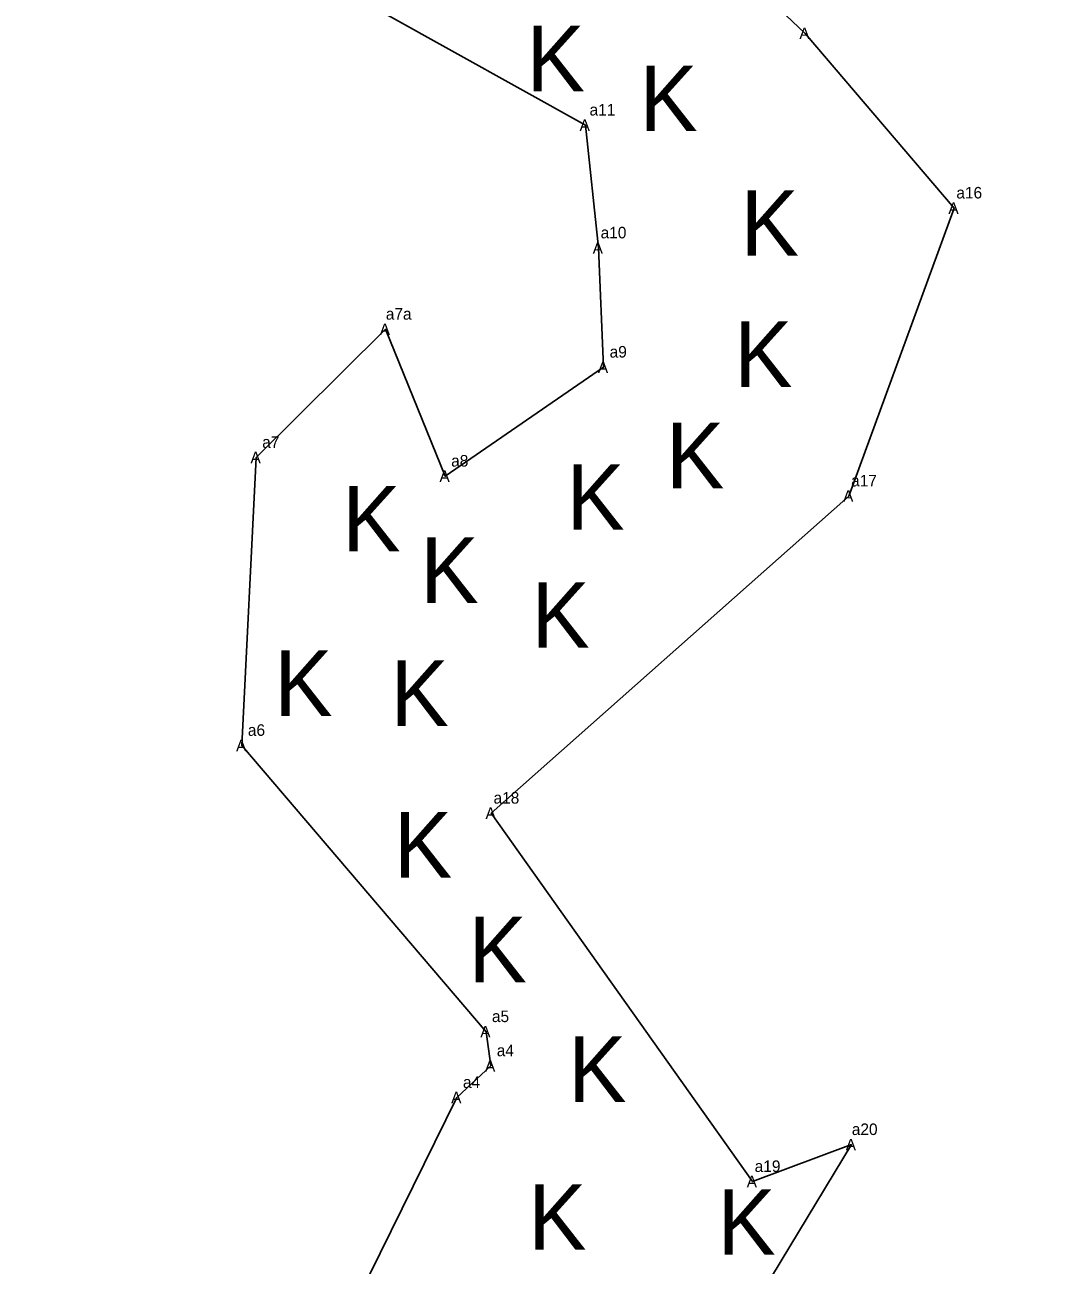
# Model space of a CAD drawing. Extents: x 2028512 to 2029541, y 737100 to 738747.
# Drawn here: x 2028890.6 to 2029023.1, y 738237.8 to 738398.9 of the extents above; entities that cross this region are included whole.
import ezdxf

# ---------------------------------------------------------------- set-up
doc = ezdxf.new("R2010")
doc.units = 0
for name, color, linetype in [('Old_Level_10', 7, 'Continuous'), ('Old_Level_20', 7, 'Continuous'), ('Old_Level_52', 7, 'Continuous'), ('Old_Level_61', 7, 'Continuous')]:
    doc.layers.add(name, color=color, linetype=linetype)

msp = doc.modelspace()

# ---------------------------------------------------------------- linework, layer by layer
at = {"layer": 'Old_Level_52'}
for points in [[(2028904.65, 738196.15), (2028890.57, 738227.25), (2028922.11, 738225.85), (2028932.53, 738230.73), (2028946.73, 738259.58), (2028951.13, 738263.7), (2028950.51, 738268.13), (2028918.78, 738305.31), (2028920.65, 738342.72), (2028937.45, 738359.38), (2028945.21, 738340.29), (2028965.8, 738354.45), (2028965.12, 738369.93), (2028963.42, 738385.89), (2028937.56, 738400.24), (2028943.82, 738411.81), (2028965.6, 738422.83), (2028991.98, 738397.81)], [(2028991.98, 738397.81), (2029011.35, 738375.11), (2028997.67, 738337.71), (2028951.19, 738296.51), (2028985.14, 738248.66), (2028998.01, 738253.46), (2028985.36, 738232.55), (2029023.05, 738224.82)]]:
    msp.add_lwpolyline(points, dxfattribs=at)

# ---------------------------------------------------------------- texts
at = {"layer": 'Old_Level_10'}
for p in [(2028955.77, 738390.3), (2028970.44, 738385.12), (2028983.6, 738368.94), (2028982.74, 738351.89), (2028973.89, 738338.72), (2028960.95, 738333.33), (2028931.83, 738330.52), (2028941.97, 738323.83), (2028956.42, 738318), (2028922.98, 738309.15), (2028938.08, 738307.86), (2028938.52, 738288.16), (2028948.22, 738274.56), (2028961.17, 738259.02), (2028955.99, 738239.81), (2028980.58, 738239.16)]:
    msp.add_text('K', height=8.5, dxfattribs=at).set_placement(p)
at = {"layer": 'Old_Level_20'}
for p in [(2028991.23, 738397.06), (2028991.23, 738397.06), (2028991.23, 738397.06), (2028991.23, 738397.06), (2028962.67, 738385.14), (2028962.67, 738385.14), (2028962.67, 738385.14), (2028962.67, 738385.14), (2029010.6, 738374.36), (2029010.6, 738374.36), (2028964.37, 738369.18), (2028964.37, 738369.18), (2028964.37, 738369.18), (2028964.37, 738369.18), (2028936.7, 738358.62), (2028936.7, 738358.62), (2028936.7, 738358.62), (2028936.7, 738358.62), (2028965.05, 738353.7), (2028965.05, 738353.7), (2028965.05, 738353.7), (2028965.05, 738353.7), (2028919.9, 738341.97), (2028919.9, 738341.97), (2028919.9, 738341.97), (2028919.9, 738341.97), (2028944.46, 738339.54), (2028944.46, 738339.54), (2028944.46, 738339.54), (2028944.46, 738339.54), (2028996.92, 738336.96), (2028996.92, 738336.96), (2028996.92, 738336.96), (2028996.92, 738336.96), (2028918.03, 738304.56), (2028918.03, 738304.56), (2028918.03, 738304.56), (2028918.03, 738304.56), (2028950.44, 738295.76), (2028950.44, 738295.76), (2028950.44, 738295.76), (2028950.44, 738295.76), (2028949.76, 738267.38), (2028949.76, 738267.38), (2028949.76, 738267.38), (2028949.76, 738267.38), (2028950.38, 738262.95), (2028950.38, 738262.95), (2028950.38, 738262.95), (2028950.38, 738262.95), (2028945.98, 738258.83), (2028945.98, 738258.83), (2028945.98, 738258.83), (2028945.98, 738258.83), (2028997.26, 738252.71), (2028997.26, 738252.71), (2028997.26, 738252.71), (2028997.26, 738252.71), (2028984.39, 738247.91), (2028984.39, 738247.91), (2028984.39, 738247.91), (2028984.39, 738247.91)]:
    msp.add_text('A', height=1.5, dxfattribs=at).set_placement(p)
at = {"layer": 'Old_Level_61'}
for s, p in [('a11', (2028963.97, 738387.14)), ('a11', (2028963.97, 738387.14)), ('a11', (2028963.97, 738387.14)), ('a11', (2028963.97, 738387.14)), ('a16', (2029011.64, 738376.36)), ('a16', (2029011.64, 738376.36)), ('a10', (2028965.41, 738371.18)), ('a10', (2028965.41, 738371.18)), ('a10', (2028965.41, 738371.18)), ('a10', (2028965.41, 738371.18)), ('a7a', (2028937.49, 738360.62)), ('a7a', (2028937.49, 738360.62)), ('a7a', (2028937.49, 738360.62)), ('a7a', (2028937.49, 738360.62)), ('a9', (2028966.58, 738355.7)), ('a9', (2028966.58, 738355.7)), ('a9', (2028966.58, 738355.7)), ('a9', (2028966.58, 738355.7)), ('a7', (2028921.42, 738343.97)), ('a7', (2028921.42, 738343.97)), ('a7', (2028921.42, 738343.97)), ('a7', (2028921.42, 738343.97)), ('a8', (2028945.98, 738341.54)), ('a8', (2028945.98, 738341.54)), ('a8', (2028945.98, 738341.54)), ('a8', (2028945.98, 738341.54)), ('a17', (2028997.96, 738338.96)), ('a17', (2028997.96, 738338.96)), ('a17', (2028997.96, 738338.96)), ('a17', (2028997.96, 738338.96)), ('a6', (2028919.56, 738306.56)), ('a6', (2028919.56, 738306.56)), ('a6', (2028919.56, 738306.56)), ('a6', (2028919.56, 738306.56)), ('a18', (2028951.49, 738297.76)), ('a18', (2028951.49, 738297.76)), ('a18', (2028951.49, 738297.76)), ('a18', (2028951.49, 738297.76)), ('a5', (2028951.28, 738269.38)), ('a5', (2028951.28, 738269.38)), ('a5', (2028951.28, 738269.38)), ('a5', (2028951.28, 738269.38)), ('a4', (2028951.91, 738264.95)), ('a4', (2028951.91, 738264.95)), ('a4', (2028951.91, 738264.95)), ('a4', (2028951.91, 738264.95)), ('a4', (2028947.51, 738260.83)), ('a4', (2028947.51, 738260.83)), ('a4', (2028947.51, 738260.83)), ('a4', (2028947.51, 738260.83)), ('a20', (2028998.05, 738254.71)), ('a20', (2028998.05, 738254.71)), ('a20', (2028998.05, 738254.71)), ('a20', (2028998.05, 738254.71)), ('a19', (2028985.43, 738249.91)), ('a19', (2028985.43, 738249.91)), ('a19', (2028985.43, 738249.91)), ('a19', (2028985.43, 738249.91))]:
    msp.add_text(s, height=1.5, dxfattribs=at).set_placement(p)

doc.saveas('drawing.dxf')
